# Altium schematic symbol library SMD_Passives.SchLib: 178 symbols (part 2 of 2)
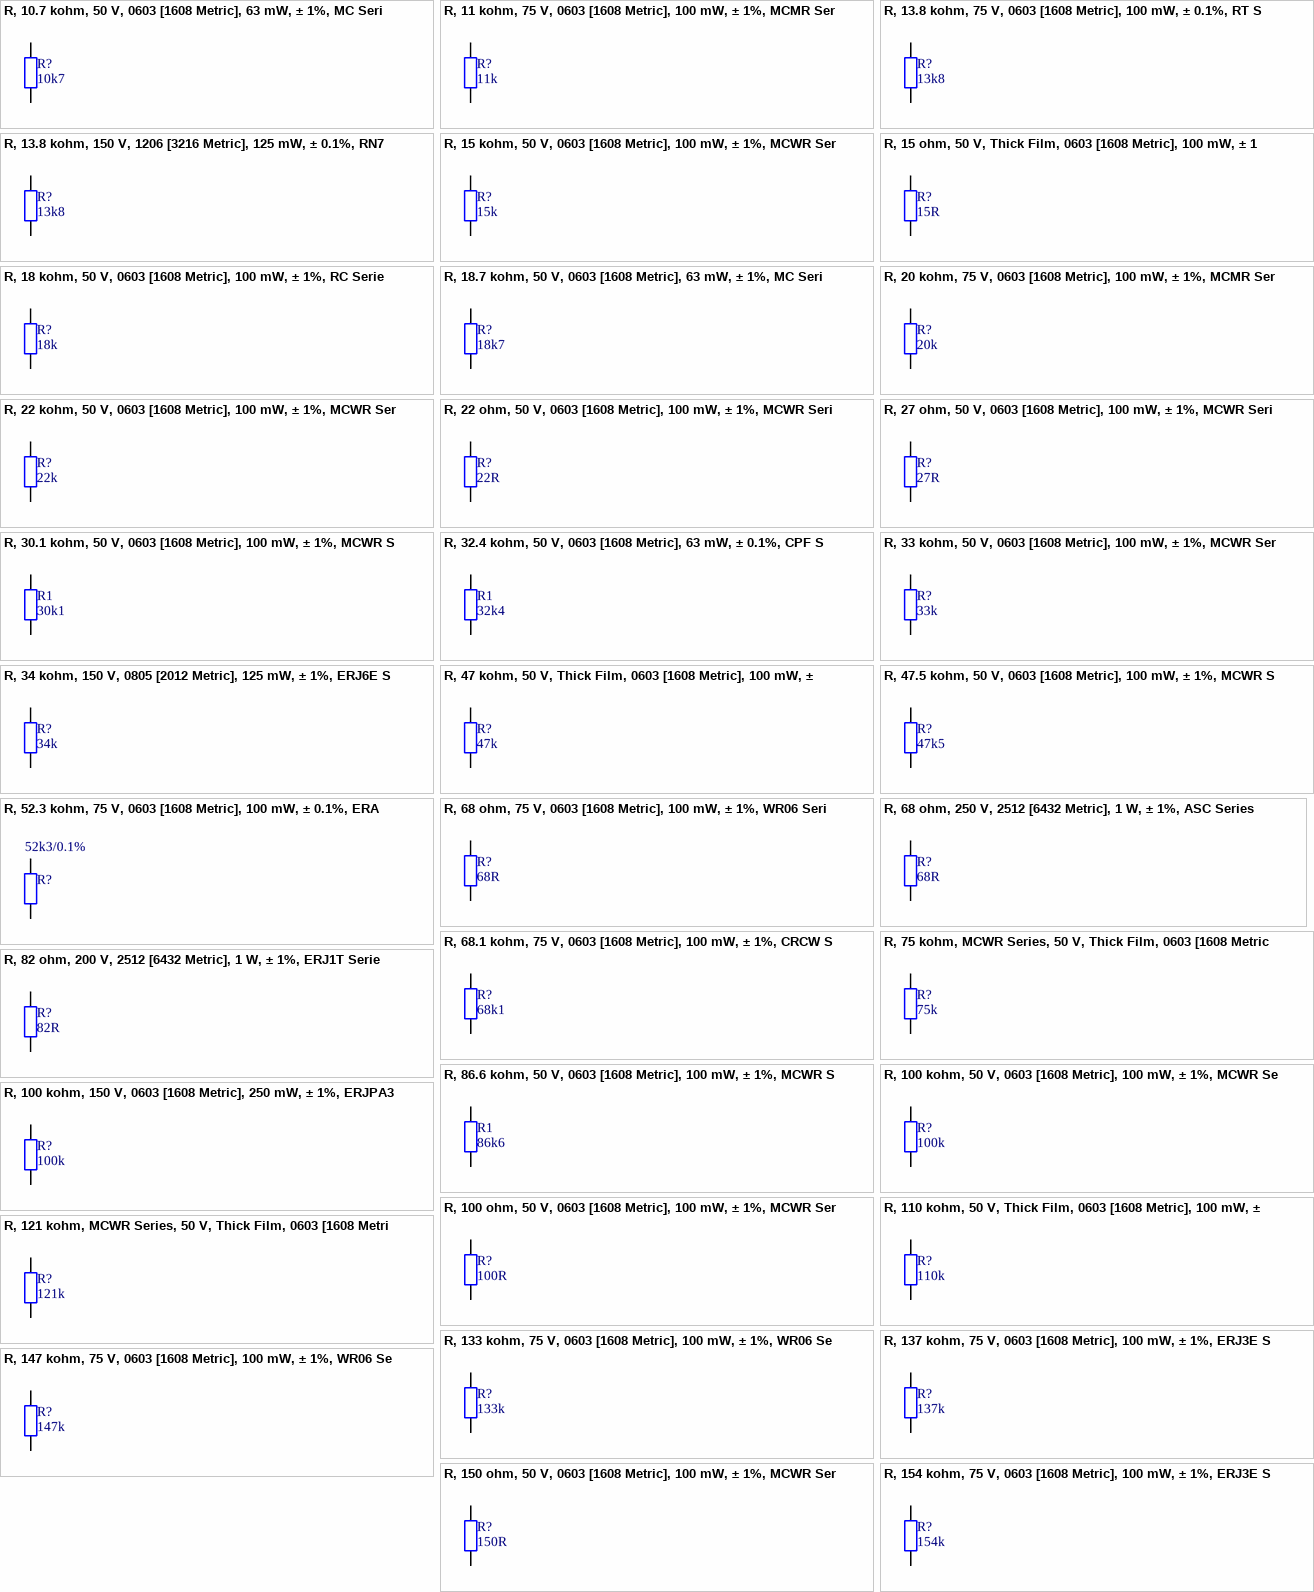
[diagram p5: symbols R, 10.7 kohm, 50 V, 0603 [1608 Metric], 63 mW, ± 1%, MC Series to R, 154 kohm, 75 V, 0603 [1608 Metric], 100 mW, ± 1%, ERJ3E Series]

## R, 47 kohm, 50 V, Thick Film, 0603 [1608 Metric], 100 mW, ± 1%
designator R?, comment 47k
SMD Chip Resistor, 47 kohm, 50 V, Thick Film, 0603 [1608 Metric], 100 mW, ± 1%; MPN: MCWR06X4702FTL; VoltageRating: 50V; Temp coefficient: *ppm; PowerRating: 100mW; MF: MULTICOMP
footprint R0402 (0402 resistor)
footprint R0603 (0603 resistor)
footprint R0805 (0805 resistor)
footprint R1206 (1206 resistor)
footprint R2512 (2512 resistor)
footprint R0201 (0201 resistor)
footprint R1210 (1210 resistor)
footprint R1812 (1812 resistor)
footprint R2010 (2010 resistor)
footprint R2512 (2512 resistor)
pins: 1, 2

## R, 47.5 kohm, 50 V, 0603 [1608 Metric], 100 mW, ± 1%, MCWR Series
designator R?, comment 47k5
SMD Chip Resistor, Thick Film, 47.5 kohm, 50 V, 0603 [1608 Metric], 100 mW, ± 1%, MCWR Series; MPN: MCWR06X4752FTL; VoltageRating: 50V; Temp coefficient: *ppm; PowerRating: 100mW; MF: MULTICOMP
footprint R0402 (0402 resistor)
footprint R0603 (0603 resistor)
footprint R0805 (0805 resistor)
footprint R1206 (1206 resistor)
footprint R2512 (2512 resistor)
footprint R0201 (0201 resistor)
footprint R1210 (1210 resistor)
footprint R1812 (1812 resistor)
footprint R2010 (2010 resistor)
footprint R2512 (2512 resistor)
pins: 1, 2

## R, 52.3 kohm, 75 V, 0603 [1608 Metric], 100 mW, ± 0.1%, ERA Series
designator R?, comment 52k3/0.1%
SMD Chip Resistor, Thin Film, 52.3 kohm, 75 V, 0603 [1608 Metric], 100 mW, ± 0.1%, ERA Series; MPN: ERA3ARB5232V; VoltageRating: 75V; Temp coefficient: *ppm; PowerRating: 100mW; MF: PANASONIC ELECTRONIC COMPONENTS; Resistance: 52k3
footprint R0402 (0402 resistor)
footprint R0603 (0603 resistor)
footprint R0805 (0805 resistor)
footprint R1206 (1206 resistor)
footprint R2512 (2512 resistor)
footprint R0201 (0201 resistor)
footprint R1210 (1210 resistor)
footprint R1812 (1812 resistor)
footprint R2010 (2010 resistor)
footprint R2512 (2512 resistor)
pins: 1, 2

## R, 68 ohm, 75 V, 0603 [1608 Metric], 100 mW, ± 1%, WR06 Series
designator R?, comment 68R
SMD Chip Resistor, 68 ohm, 75 V, 0603 [1608 Metric], 100 mW, ± 1%, WR06 Series; MPN: WR06X68R0FTL; VoltageRating: 75V; Temp coefficient: *ppm; PowerRating: 100mW; MF: WALSIN
footprint R0402 (0402 resistor)
footprint R0603 (0603 resistor)
footprint R0805 (0805 resistor)
footprint R1206 (1206 resistor)
footprint R2512 (2512 resistor)
footprint R0201 (0201 resistor)
footprint R1210 (1210 resistor)
footprint R1812 (1812 resistor)
footprint R2010 (2010 resistor)
footprint R2512 (2512 resistor)
pins: 1, 2

## R, 68 ohm, 250 V, 2512 [6432 Metric], 1 W, ± 1%, ASC Series
designator R?, comment 68R
SMD Chip Resistor, Thick Film, 68 ohm, 250 V, 2512 [6432 Metric], 1 W, ± 1%, ASC Series; MPN: ASC2512-68RFT4; VoltageRating: 250V; Temp coefficient: *ppm; PowerRating: 1W; MF: WELWYN
footprint R2512 (2512 resistor)
pins: 1, 2

## R, 68.1 kohm, 75 V, 0603 [1608 Metric], 100 mW, ± 1%, CRCW Series
designator R?, comment 68k1
SMD Chip Resistor, Thick Film, 68.1 kohm, 75 V, 0603 [1608 Metric], 100 mW, ± 1%, CRCW Series; MPN: CRCW060368K1FKEA.; VoltageRating: 75V; Temp coefficient: *ppm; PowerRating: 100mW; MF: VISHAY
footprint R0402 (0402 resistor)
footprint R0603 (0603 resistor)
footprint R0805 (0805 resistor)
footprint R1206 (1206 resistor)
footprint R2512 (2512 resistor)
footprint R0201 (0201 resistor)
footprint R1210 (1210 resistor)
footprint R1812 (1812 resistor)
footprint R2010 (2010 resistor)
footprint R2512 (2512 resistor)
pins: 1, 2

## R, 75 kohm, MCWR Series, 50 V, Thick Film, 0603 [1608 Metric], 100 mW
designator R?, comment 75k
SMD Chip Resistor, 75 kohm, MCWR Series, 50 V, Thick Film, 0603 [1608 Metric], 100 mW; MPN: MCWR06X7502FTL; Precision: 1%; VoltageRating: 50V; PowerRating: 100mW; MF: MULTICOMP
footprint R0603 (0603 resistor)
pins: 1, 2

## R, 82 ohm, 200 V, 2512 [6432 Metric], 1 W, ± 1%, ERJ1T Series
designator R?, comment 82R
SMD Chip Resistor, Thick Film, 82 ohm, 200 V, 2512 [6432 Metric], 1 W, ± 1%, ERJ1T Series; MPN: ERJ1TNF82R0U; VoltageRating: 200V; Temp coefficient: *ppm; PowerRating: 1W; MF: PANASONIC ELECTRONIC COMPONENTS
footprint R2512 (2512 resistor)
pins: 1, 2

## R, 86.6 kohm, 50 V, 0603 [1608 Metric], 100 mW, ± 1%, MCWR Series
designator R1, comment 86k6
SMD Chip Resistor, Thick Film, 86.6 kohm, 50 V, 0603 [1608 Metric], 100 mW, ± 1%, MCWR Series; MPN: MCWR06X8662FTL; VoltageRating: 50V; Temp coefficient: *ppm; PowerRating: 100mW; MF: MULTICOMP
footprint R0603 (0603 resistor)
pins: 1, 2

## R, 100 kohm, 50 V, 0603 [1608 Metric], 100 mW, ± 1%, MCWR Series
designator R?, comment 100k
SMD Chip Resistor, Thick Film, 100 kohm, 50 V, 0603 [1608 Metric], 100 mW, ± 1%, MCWR Series; MPN: MCWR06X1003FTL; Temp coefficient: *ppm; MF: MULTICOMP
footprint R0603 (0603 resistor)
pins: 1, 2

## R, 100 kohm, 150 V, 0603 [1608 Metric], 250 mW, ± 1%, ERJPA3 Series
designator R?, comment 100k
SMD Chip Resistor, Thick Film, 100 kohm, 150 V, 0603 [1608 Metric], 250 mW, ± 1%, ERJPA3 Series; MPN: ERJPA3F1003V; VoltageRating: 150V; Temp coefficient: *ppm; PowerRating: 250mW; MF: PANASONIC ELECTRONIC COMPONENTS
footprint R0603 (0603 resistor)
pins: 1, 2

## R, 100 ohm, 50 V, 0603 [1608 Metric], 100 mW, ± 1%, MCWR Series
designator R?, comment 100R
SMD Chip Resistor, Thick Film, 100 ohm, 50 V, 0603 [1608 Metric], 100 mW, ± 1%, MCWR Series; MPN: MCWR06X1000FTL; VoltageRating: 50V; Temp coefficient: *ppm; PowerRating: 100mW; MF: MULTICOMP
footprint R0603 (0603 resistor)
pins: 1, 2

## R, 110 kohm, 50 V, Thick Film, 0603 [1608 Metric], 100 mW, ± 1%
designator R?, comment 110k
SMD Chip Resistor, 110 kohm, 50 V, Thick Film, 0603 [1608 Metric], 100 mW, ± 1%; MPN: MCWR06X1103FTL; VoltageRating: 50V; Temp coefficient: *ppm; PowerRating: 100mW; MF: MULTICOMP
footprint R0603 (0603 resistor)
pins: 1, 2

## R, 121 kohm, MCWR Series, 50 V, Thick Film, 0603 [1608 Metric], 100 mW
designator R?, comment 121k
SMD Chip Resistor, 121 kohm, MCWR Series, 50 V, Thick Film, 0603 [1608 Metric], 100 mW; MPN: MCWR06X1213FTL; Precision: 1%; VoltageRating: 50V; PowerRating: 100mW; MF: MULTICOMP
footprint R0603 (0603 resistor)
pins: 1, 2

## R, 133 kohm, 75 V, 0603 [1608 Metric], 100 mW, ± 1%, WR06 Series
designator R?, comment 133k
SMD Chip Resistor, 133 kohm, 75 V, 0603 [1608 Metric], 100 mW, ± 1%, WR06 Series; MPN: MCMR06X1653FTL; VoltageRating: 75V; Temp coefficient: *ppm; PowerRating: 100mW; MF: WALSIN
footprint R0402 (0402 resistor)
footprint R0603 (0603 resistor)
footprint R0805 (0805 resistor)
footprint R1206 (1206 resistor)
footprint R2512 (2512 resistor)
footprint R0201 (0201 resistor)
footprint R1210 (1210 resistor)
footprint R1812 (1812 resistor)
footprint R2010 (2010 resistor)
footprint R2512 (2512 resistor)
pins: 1, 2

## R, 137 kohm, 75 V, 0603 [1608 Metric], 100 mW, ± 1%, ERJ3E Series
designator R?, comment 137k
SMD Chip Resistor, Thick Film, 137 kohm, 75 V, 0603 [1608 Metric], 100 mW, ± 1%, ERJ3E Series; MPN: ERJ3EKF1373V; VoltageRating: 75V; Temp coefficient: *ppm; PowerRating: 100mW; MF: PANASONIC ELECTRONIC COMPONENTS
footprint R0603 (0603 resistor)
pins: 1, 2

## R, 147 kohm, 75 V, 0603 [1608 Metric], 100 mW, ± 1%, WR06 Series
designator R?, comment 147k
SMD Chip Resistor, 147 kohm, 75 V, 0603 [1608 Metric], 100 mW, ± 1%, WR06 Series; MPN: WR06X1473FTL; VoltageRating: 75V; Temp coefficient: *ppm; PowerRating: 100mW; MF: WALSIN
footprint R0402 (0402 resistor)
footprint R0603 (0603 resistor)
footprint R0805 (0805 resistor)
footprint R1206 (1206 resistor)
footprint R2512 (2512 resistor)
footprint R0201 (0201 resistor)
footprint R1210 (1210 resistor)
footprint R1812 (1812 resistor)
footprint R2010 (2010 resistor)
footprint R2512 (2512 resistor)
pins: 1, 2

## R, 150 ohm, 50 V, 0603 [1608 Metric], 100 mW, ± 1%, MCWR Series
designator R?, comment 150R
SMD Chip Resistor, Thick Film, 150 ohm, 50 V, 0603 [1608 Metric], 100 mW, ± 1%, MCWR Series; MPN: MCWR06X1500FTL; VoltageRating: 50V; Temp coefficient: *ppm; PowerRating: 100mW; MF: MULTICOMP
footprint R0603 (0603 resistor)
pins: 1, 2

## R, 154 kohm, 75 V, 0603 [1608 Metric], 100 mW, ± 1%, ERJ3E Series
designator R?, comment 154k
SMD Chip Resistor, Thick Film, 154 kohm, 75 V, 0603 [1608 Metric], 100 mW, ± 1%, ERJ3E Series; MPN: ERJ3EKF1543V; VoltageRating: 75V; Temp coefficient: *ppm; PowerRating: 100mW; MF: PANASONIC ELECTRONIC COMPONENTS
footprint R0402 (0402 resistor)
footprint R0603 (0603 resistor)
footprint R0805 (0805 resistor)
footprint R1206 (1206 resistor)
footprint R2512 (2512 resistor)
footprint R0201 (0201 resistor)
footprint R1210 (1210 resistor)
footprint R1812 (1812 resistor)
footprint R2010 (2010 resistor)
footprint R2512 (2512 resistor)
pins: 1, 2

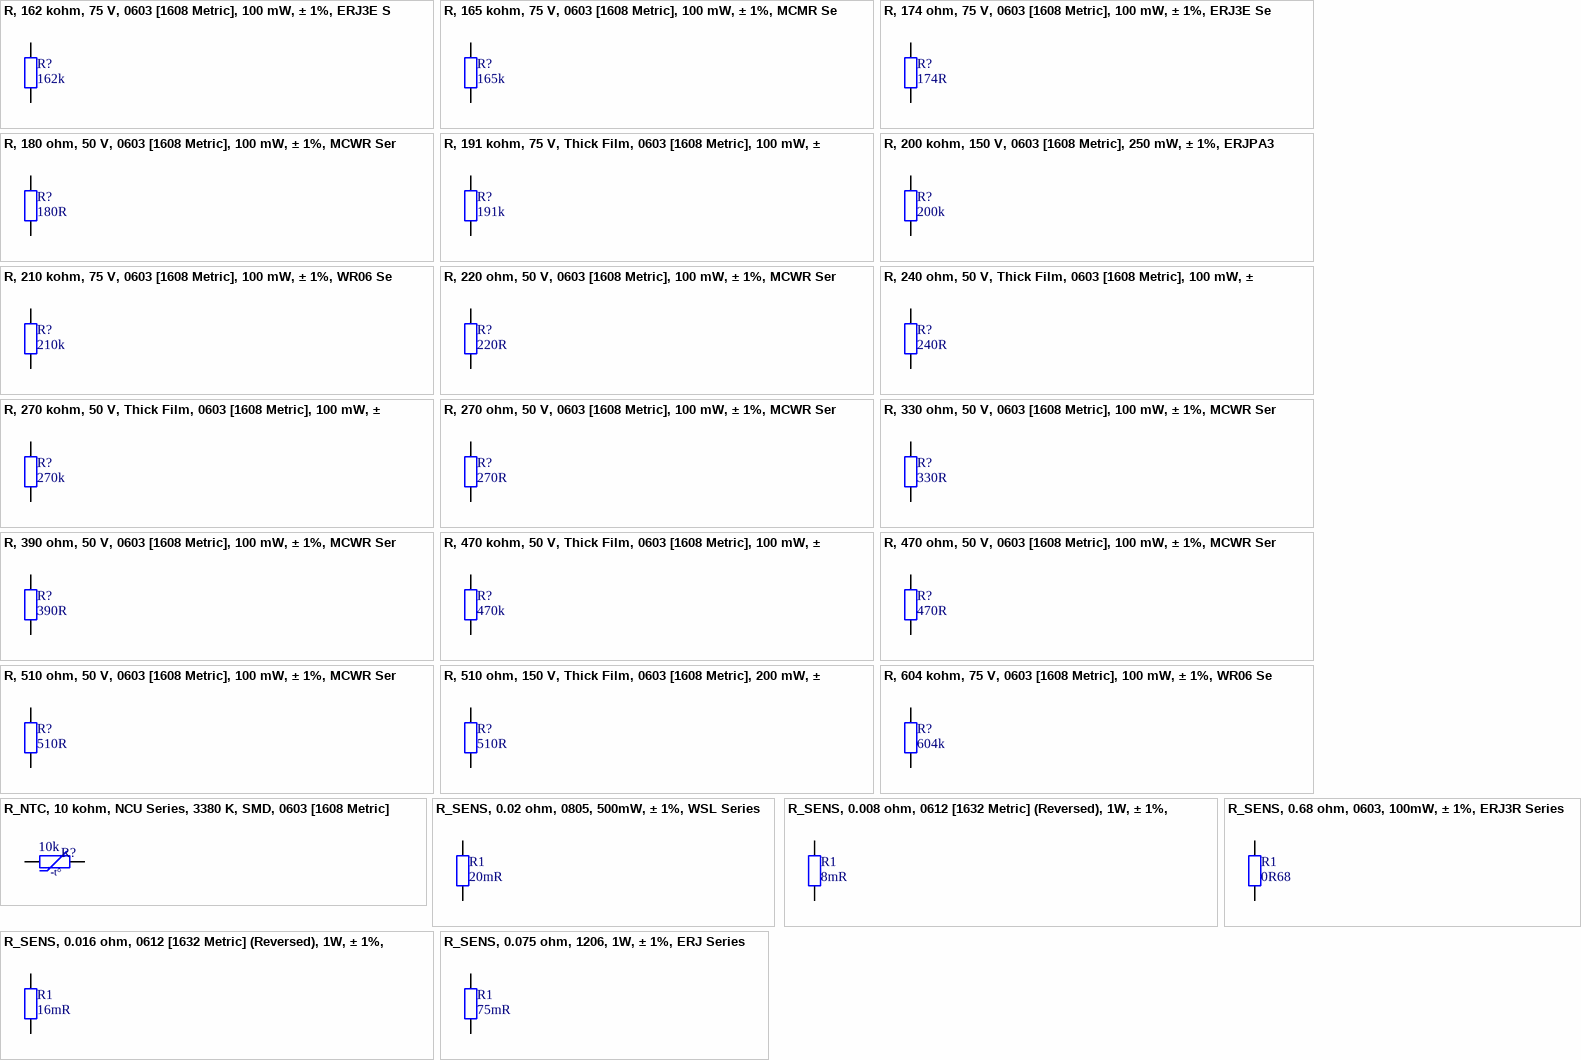
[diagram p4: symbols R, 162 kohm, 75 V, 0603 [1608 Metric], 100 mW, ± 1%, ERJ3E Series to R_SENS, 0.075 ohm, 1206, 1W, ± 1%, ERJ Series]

## R, 162 kohm, 75 V, 0603 [1608 Metric], 100 mW, ± 1%, ERJ3E Series
designator R?, comment 162k
SMD Chip Resistor, Thick Film, 162 kohm, 75 V, 0603 [1608 Metric], 100 mW, ± 1%, ERJ3E Series; MPN: ERJ3EKF1623V; VoltageRating: 75V; Temp coefficient: *ppm; PowerRating: 100mW; MF: PANASONIC ELECTRONIC COMPONENTS
footprint R0603 (0603 resistor)
pins: 1, 2

## R, 165 kohm, 75 V, 0603 [1608 Metric], 100 mW, ± 1%, MCMR Series
designator R?, comment 165k
SMD Chip Resistor, Ceramic, 165 kohm, 75 V, 0603 [1608 Metric], 100 mW, ± 1%, MCMR Series; MPN: MCMR06X1653FTL; VoltageRating: 75V; Temp coefficient: *ppm; PowerRating: 100mW; MF: MULTICOMP
footprint R0402 (0402 resistor)
footprint R0603 (0603 resistor)
footprint R0805 (0805 resistor)
footprint R1206 (1206 resistor)
footprint R2512 (2512 resistor)
footprint R0201 (0201 resistor)
footprint R1210 (1210 resistor)
footprint R1812 (1812 resistor)
footprint R2010 (2010 resistor)
footprint R2512 (2512 resistor)
pins: 1, 2

## R, 174 ohm, 75 V, 0603 [1608 Metric], 100 mW, ± 1%, ERJ3E Series
designator R?, comment 174R
SMD Chip Resistor, Thick Film, 10 ohm, 50 V, 0603 [1608 Metric], 100 mW, ± 1%, MCWR Series; MPN: ERJ3EKF1740V; VoltageRating: 75V; Temp coefficient: *ppm; PowerRating: 100mW; MF: PANASONIC ELECTRONIC COMPONENTS
footprint R0402 (0402 resistor)
footprint R0603 (0603 resistor)
footprint R0805 (0805 resistor)
footprint R1206 (1206 resistor)
footprint R2512 (2512 resistor)
footprint R0201 (0201 resistor)
footprint R1210 (1210 resistor)
footprint R1812 (1812 resistor)
footprint R2010 (2010 resistor)
footprint R2512 (2512 resistor)
pins: 1, 2

## R, 180 ohm, 50 V, 0603 [1608 Metric], 100 mW, ± 1%, MCWR Series
designator R?, comment 180R
SMD Chip Resistor, Thick Film, 180 ohm, 50 V, 0603 [1608 Metric], 100 mW, ± 1%, MCWR Series; MPN: MCWR06X1800FTL; VoltageRating: 50V; Temp coefficient: *ppm; PowerRating: 100mW; MF: MULTICOMP
footprint R0603 (0603 resistor)
pins: 1, 2

## R, 191 kohm, 75 V, Thick Film, 0603 [1608 Metric], 100 mW, ± 1%
designator R?, comment 191k
SMD Chip Resistor, 191 kohm, 75 V, Thick Film, 0603 [1608 Metric], 100 mW, ± 1%; MPN: ERJ3EKF1913V; VoltageRating: 75V; Temp coefficient: *ppm; PowerRating: 100mW; MF: PANASONIC ELECTRONIC COMPONENTS
footprint R0402 (0402 resistor)
footprint R0603 (0603 resistor)
footprint R0805 (0805 resistor)
footprint R1206 (1206 resistor)
footprint R2512 (2512 resistor)
footprint R0201 (0201 resistor)
footprint R1210 (1210 resistor)
footprint R1812 (1812 resistor)
footprint R2010 (2010 resistor)
footprint R2512 (2512 resistor)
pins: 1, 2

## R, 200 kohm, 150 V, 0603 [1608 Metric], 250 mW, ± 1%, ERJPA3 Series
designator R?, comment 200k
SMD Chip Resistor, Thick Film, 200 kohm, 150 V, 0603 [1608 Metric], 250 mW, ± 1%, ERJPA3 Series; MPN: ERJPA3F2003V; VoltageRating: 150V; Temp coefficient: *ppm; PowerRating: 250mW; MF: PANASONIC ELECTRONIC COMPONENTS
footprint R0402 (0402 resistor)
footprint R0603 (0603 resistor)
footprint R0805 (0805 resistor)
footprint R1206 (1206 resistor)
footprint R2512 (2512 resistor)
footprint R0201 (0201 resistor)
footprint R1210 (1210 resistor)
footprint R1812 (1812 resistor)
footprint R2010 (2010 resistor)
footprint R2512 (2512 resistor)
pins: 1, 2

## R, 210 kohm, 75 V, 0603 [1608 Metric], 100 mW, ± 1%, WR06 Series
designator R?, comment 210k
SMD Chip Resistor, 210 kohm, 75 V, 0603 [1608 Metric], 100 mW, ± 1%, WR06 Series; MPN: WR06X2103FTL; VoltageRating: 75V; Temp coefficient: *ppm; PowerRating: 100mW; MF: WALSIN
footprint R0603 (0603 resistor)
pins: 1, 2

## R, 220 ohm, 50 V, 0603 [1608 Metric], 100 mW, ± 1%, MCWR Series
designator R?, comment 220R
SMD Chip Resistor, Thick Film, 220 ohm, 50 V, 0603 [1608 Metric], 100 mW, ± 1%, MCWR Series; MPN: MCWR06X2200FTL; VoltageRating: 50V; Temp coefficient: *ppm; PowerRating: 100mW; MF: MULTICOMP
footprint R0603 (0603 resistor)
pins: 1, 2

## R, 240 ohm, 50 V, Thick Film, 0603 [1608 Metric], 100 mW, ± 1%
designator R?, comment 240R
SMD Chip Resistor, 240 ohm, 50 V, Thick Film, 0603 [1608 Metric], 100 mW, ± 1%; MPN: MCWR06X2400FTL; VoltageRating: 50V; Temp coefficient: *ppm; PowerRating: 100mW; MF: MULTICOMP
footprint R0402 (0402 resistor)
footprint R0603 (0603 resistor)
footprint R0805 (0805 resistor)
footprint R1206 (1206 resistor)
footprint R2512 (2512 resistor)
footprint R0201 (0201 resistor)
footprint R1210 (1210 resistor)
footprint R1812 (1812 resistor)
footprint R2010 (2010 resistor)
footprint R2512 (2512 resistor)
pins: 1, 2

## R, 270 kohm, 50 V, Thick Film, 0603 [1608 Metric], 100 mW, ± 1%
designator R?, comment 270k
SMD Chip Resistor, 270 kohm, 50 V, Thick Film, 0603 [1608 Metric], 100 mW, ± 1%; MPN: MCWR06X2703FTL; VoltageRating: 50V; PowerRating: 100mW; MF: MULTICOMP
footprint R0603 (0603 resistor)
pins: 1, 2

## R, 270 ohm, 50 V, 0603 [1608 Metric], 100 mW, ± 1%, MCWR Series
designator R?, comment 270R
SMD Chip Resistor, Thick Film, 270 ohm, 50 V, 0603 [1608 Metric], 100 mW, ± 1%, MCWR Series; MPN: MCWR06X2700FTL; VoltageRating: 50V; PowerRating: 100mW; MF: MULTICOMP
footprint R0603 (0603 resistor)
pins: 1, 2

## R, 330 ohm, 50 V, 0603 [1608 Metric], 100 mW, ± 1%, MCWR Series
designator R?, comment 330R
SMD Chip Resistor, Thick Film, 330 ohm, 50 V, 0603 [1608 Metric], 100 mW, ± 1%, MCWR Series; MPN: MCWR06X3900FTL; VoltageRating: 50V; Temp coefficient: *ppm; PowerRating: 100mW; MF: MULTICOMP
footprint R0603 (0603 resistor)
pins: 1, 2

## R, 390 ohm, 50 V, 0603 [1608 Metric], 100 mW, ± 1%, MCWR Series
designator R?, comment 390R
SMD Chip Resistor, Thick Film, 390 ohm, 50 V, 0603 [1608 Metric], 100 mW, ± 1%, MCWR Series; MPN: MCWR06X3900FTL; VoltageRating: 50V; Temp coefficient: *ppm; PowerRating: 100mW; MF: MULTICOMP
footprint R0603 (0603 resistor)
pins: 1, 2

## R, 470 kohm, 50 V, Thick Film, 0603 [1608 Metric], 100 mW, ± 1%
designator R?, comment 470k
SMD Chip Resistor, 470 kohm, 50 V, Thick Film, 0603 [1608 Metric], 100 mW, ± 1%; MPN: MCWR06X4703FTL; VoltageRating: 50V; Temp coefficient: *ppm; PowerRating: 100mW; MF: MULTICOMP
footprint R0402 (0402 resistor)
footprint R0603 (0603 resistor)
footprint R0805 (0805 resistor)
footprint R1206 (1206 resistor)
footprint R2512 (2512 resistor)
footprint R0201 (0201 resistor)
footprint R1210 (1210 resistor)
footprint R1812 (1812 resistor)
footprint R2010 (2010 resistor)
footprint R2512 (2512 resistor)
pins: 1, 2

## R, 470 ohm, 50 V, 0603 [1608 Metric], 100 mW, ± 1%, MCWR Series
designator R?, comment 470R
SMD Chip Resistor, Thick Film, 470 ohm, 50 V, 0603 [1608 Metric], 100 mW, ± 1%, MCWR Series; MPN: MCWR06X4700FTL; VoltageRating: 50V; Temp coefficient: *ppm; PowerRating: 100mW; MF: MULTICOMP
footprint R0603 (0603 resistor)
pins: 1, 2

## R, 510 ohm, 50 V, 0603 [1608 Metric], 100 mW, ± 1%, MCWR Series
designator R?, comment 510R
SMD Chip Resistor, Thick Film, 510 ohm, 50 V, 0603 [1608 Metric], 100 mW, ± 1%, MCWR Series; MPN: MCWR06X5100FTL; VoltageRating: 50V; Temp coefficient: *ppm; PowerRating: 100mW; MF: MULTICOMP
footprint R0603 (0603 resistor)
pins: 1, 2

## R, 510 ohm, 150 V, Thick Film, 0603 [1608 Metric], 200 mW, ± 1%
designator R?, comment 510R
SMD Chip Resistor, 510 ohm, 150 V, Thick Film, 0603 [1608 Metric], 200 mW, ± 1%; MPN: ERJP03F5100V; VoltageRating: 150V; Temp coefficient: *ppm; PowerRating: 200mW; MF: PANASONIC ELECTRONIC COMPONENTS
footprint R0603 (0603 resistor)
pins: 1, 2

## R, 604 kohm, 75 V, 0603 [1608 Metric], 100 mW, ± 1%, WR06 Series
designator R?, comment 604k
SMD Chip Resistor, 604 kohm, 75 V, 0603 [1608 Metric], 100 mW, ± 1%, WR06 Series; MPN: WR06X6043FTL; VoltageRating: 75V; Temp coefficient: *ppm; PowerRating: 100mW; MF: WALSIN
footprint R0402 (0402 resistor)
footprint R0603 (0603 resistor)
footprint R0805 (0805 resistor)
footprint R1206 (1206 resistor)
footprint R2512 (2512 resistor)
footprint R0201 (0201 resistor)
footprint R1210 (1210 resistor)
footprint R1812 (1812 resistor)
footprint R2010 (2010 resistor)
footprint R2512 (2512 resistor)
pins: 1, 2

## R_NTC, 10 kohm, NCU Series, 3380 K, SMD, 0603 [1608 Metric]
designator R?, comment Resistance: 10k  (hidden comment: 10k NTC)
Thermistor, NTC, 10 kohm, NCU Series, 3380 K, SMD, 0603 [1608 Metric]; MPN: MCMR06X1653FTL; Precision: 1%; Beta Value: 3380K; Temp coefficient: *ppm; MF: MULTICOMP
footprint R0402 (0402 resistor)
footprint R0603 (0603 resistor)
footprint R0805 (0805 resistor)
footprint R1206 (1206 resistor)
footprint R2512 (2512 resistor)
footprint R0201 (0201 resistor)
footprint R1210 (1210 resistor)
footprint R1812 (1812 resistor)
footprint R2010 (2010 resistor)
footprint R2512 (2512 resistor)
pins: 1, 2

## R_SENS, 0.02 ohm, 0805, 500mW, ± 1%, WSL Series
designator R1, comment 20mR
METAL STRIP RESISTOR, 0.02 OHM, 500mW, 805, 1%; MPN: WSLP0805R0200FEA; Temp coefficient: *ppm; MF: VISHAY
footprint R0805 (0805 resistor)
pins: 1, 2

## R_SENS, 0.008 ohm, 0612 [1632 Metric] (Reversed), 1W, ± 1%, PRL Series
designator R1, comment 8mR
SMD Chip Resistor, Thick Film, Current Sense Resistors - SMD 1W 0.008ohm 1%; MPN: PRL1632-R008-F-T1; VoltageRating: 50V; Temp coefficient: *ppm; MF: SUSUMU
footprint 0612 (Reversed) (Chip Resistor, 2-Leads, Body 1,60x3,20mm, IPC Medium Density)
pins: 1, 2

## R_SENS, 0.016 ohm, 0612 [1632 Metric] (Reversed), 1W, ± 1%, PRL Series
designator R1, comment 16mR
SMD Chip Resistor, Thick Film, Current Sense Resistors - SMD 1W 0.016ohm 1%; MPN: MCWR06X1004FTL; VoltageRating: 50V; Temp coefficient: *ppm; MF: MULTICOMP
footprint 0612 (Reversed) (Chip Resistor, 2-Leads, Body 1,60x3,20mm, IPC Medium Density)
pins: 1, 2

## R_SENS, 0.68 ohm, 0603, 100mW, ± 1%, ERJ3R Series
designator R1, comment 0R68
SMD Current Sense Resistor, 0.68 ohm, ERJ3R Series, 0603 [1608 Metric], 100 mW, ± 1%, Thick Film; MPN: ERJ3RQFR68V; Temp coefficient: *ppm; PowerRating: 100mW; MF: Panasonic Electronic Components
footprint R0603 (0603 resistor)
pins: 1, 2

## R_SENS, 0.075 ohm, 1206, 1W, ± 1%, ERJ Series
designator R1, comment 75mR
SMD Chip Resistor, Thick Film, Current Sense Resistors - SMD 1W 0.075ohm 1%; MPN: ERJ-8BWFR075V; VoltageRating: 50V; Temp coefficient: *ppm; MF: Panasonic Electronic Components
footprint R1206 (1206 resistor)
pins: 1, 2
